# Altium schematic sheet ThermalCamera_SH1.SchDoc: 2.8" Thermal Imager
size 647 x 419 mm; Author: Steve Hageman; DrawnBy: Steve Hageman; DocumentNumber: 2019-02-21; Revision: B1; SheetNumber: 1; SheetTotal: 1; PageSetup: Record=PageOptions¦CenterHorizontal=True¦CenterVertical=True¦PrintScale=1.00¦XCorrection=1.00¦YCorrection=1.00¦PrintKind=0¦BorderSize=5000000¦LeftOffset=0¦BottomOffset=0¦Orientation=2¦PaperLength=1000¦PaperWidth=1000¦Scale=100¦PaperSource=15¦PrintQuality=600¦MediaType=1¦DitherType=10¦PaperKind=Letter¦PrintScaleMode=1
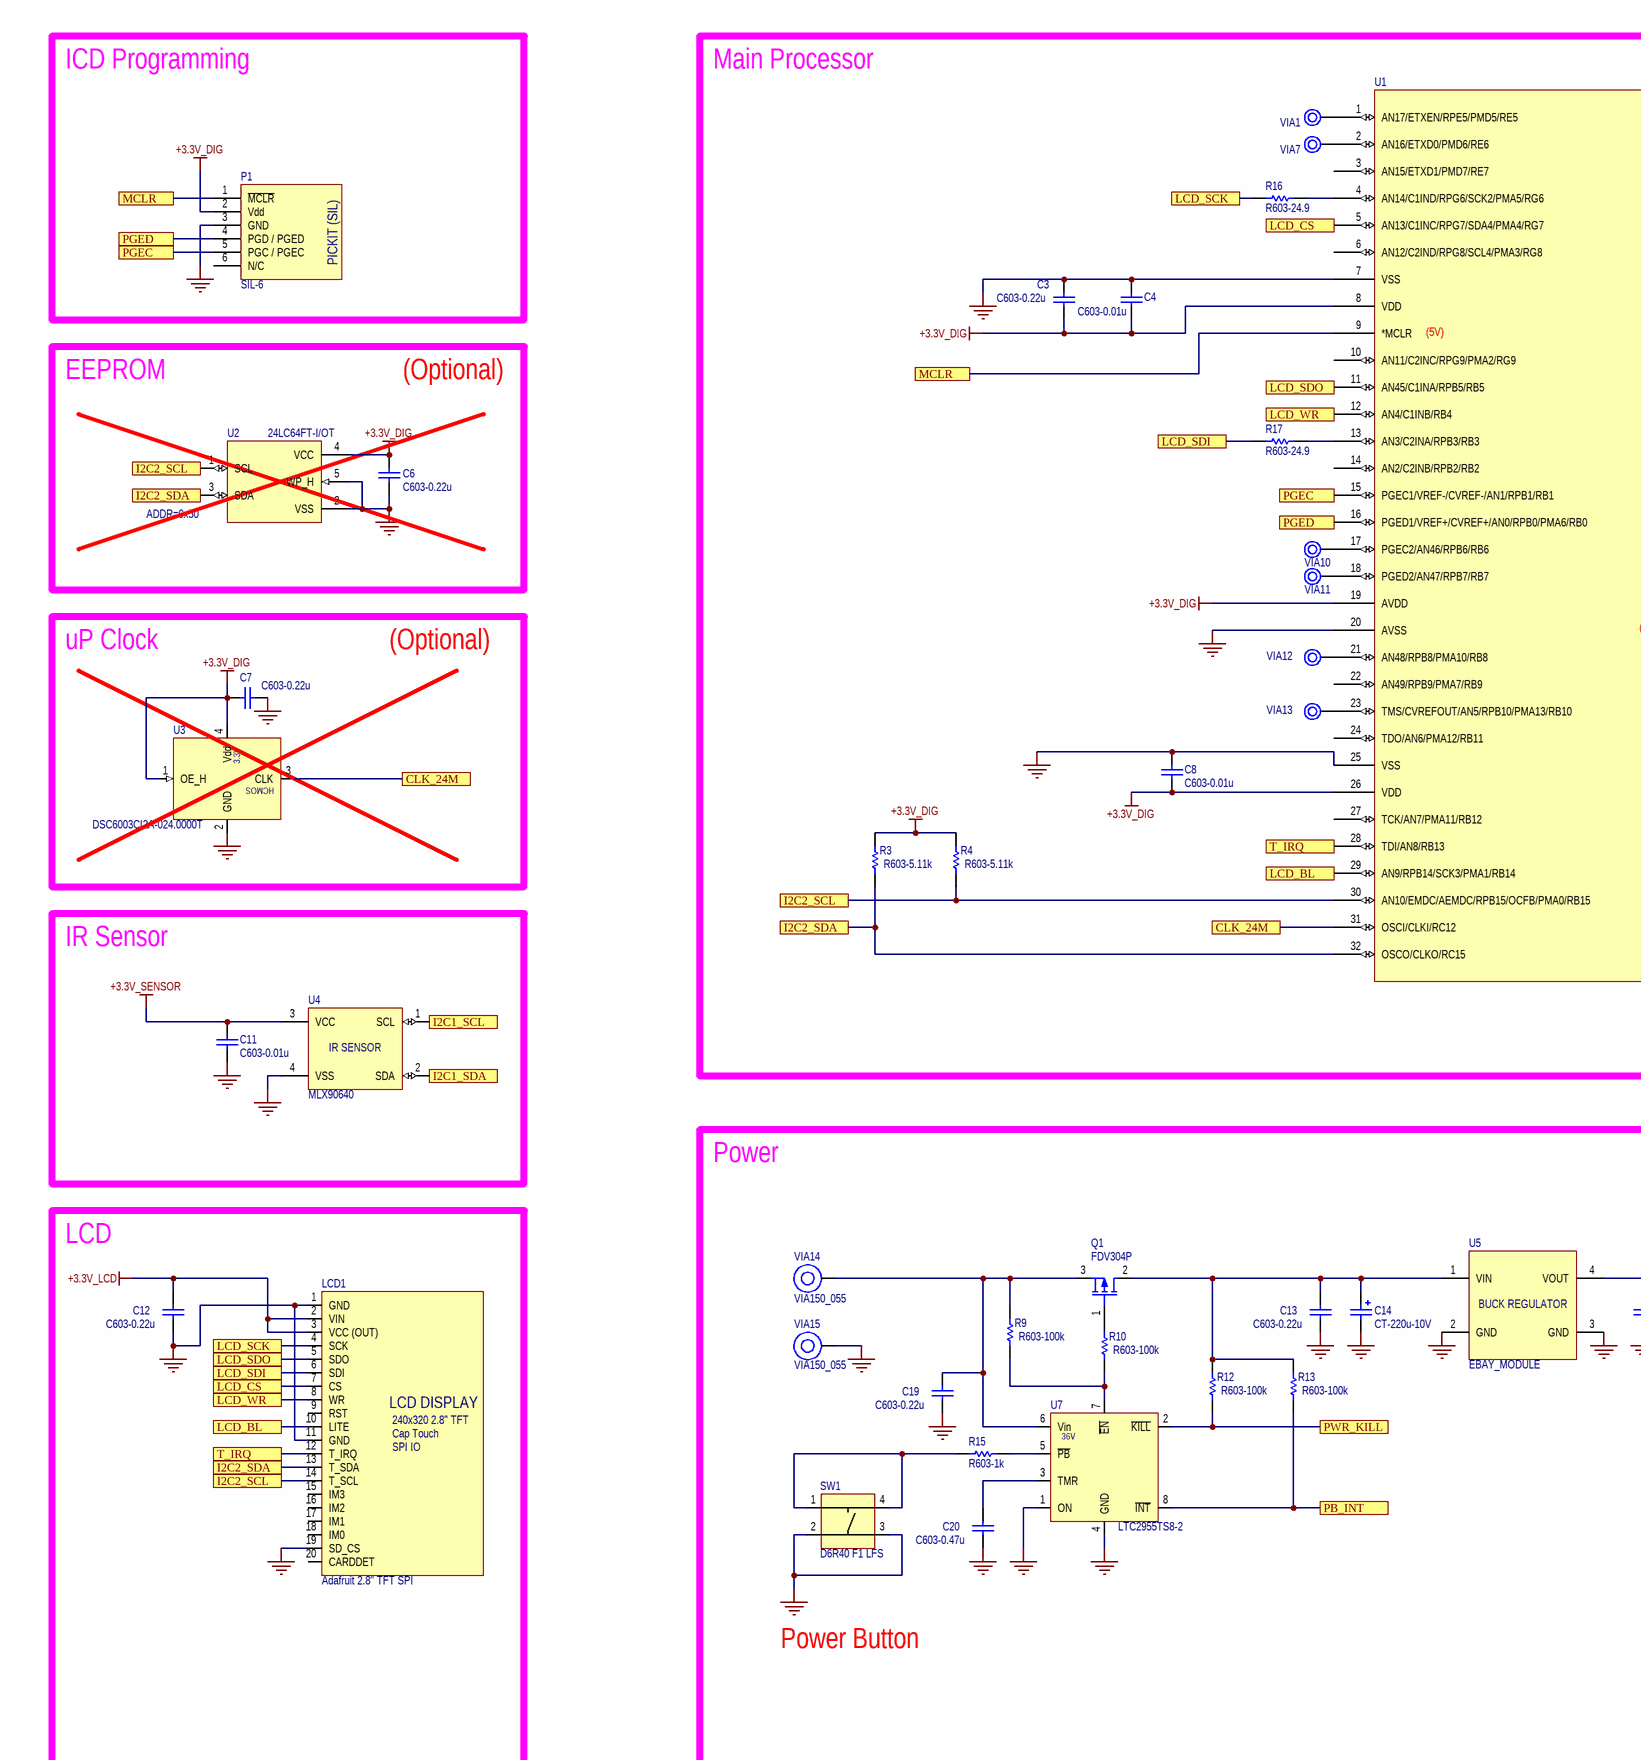
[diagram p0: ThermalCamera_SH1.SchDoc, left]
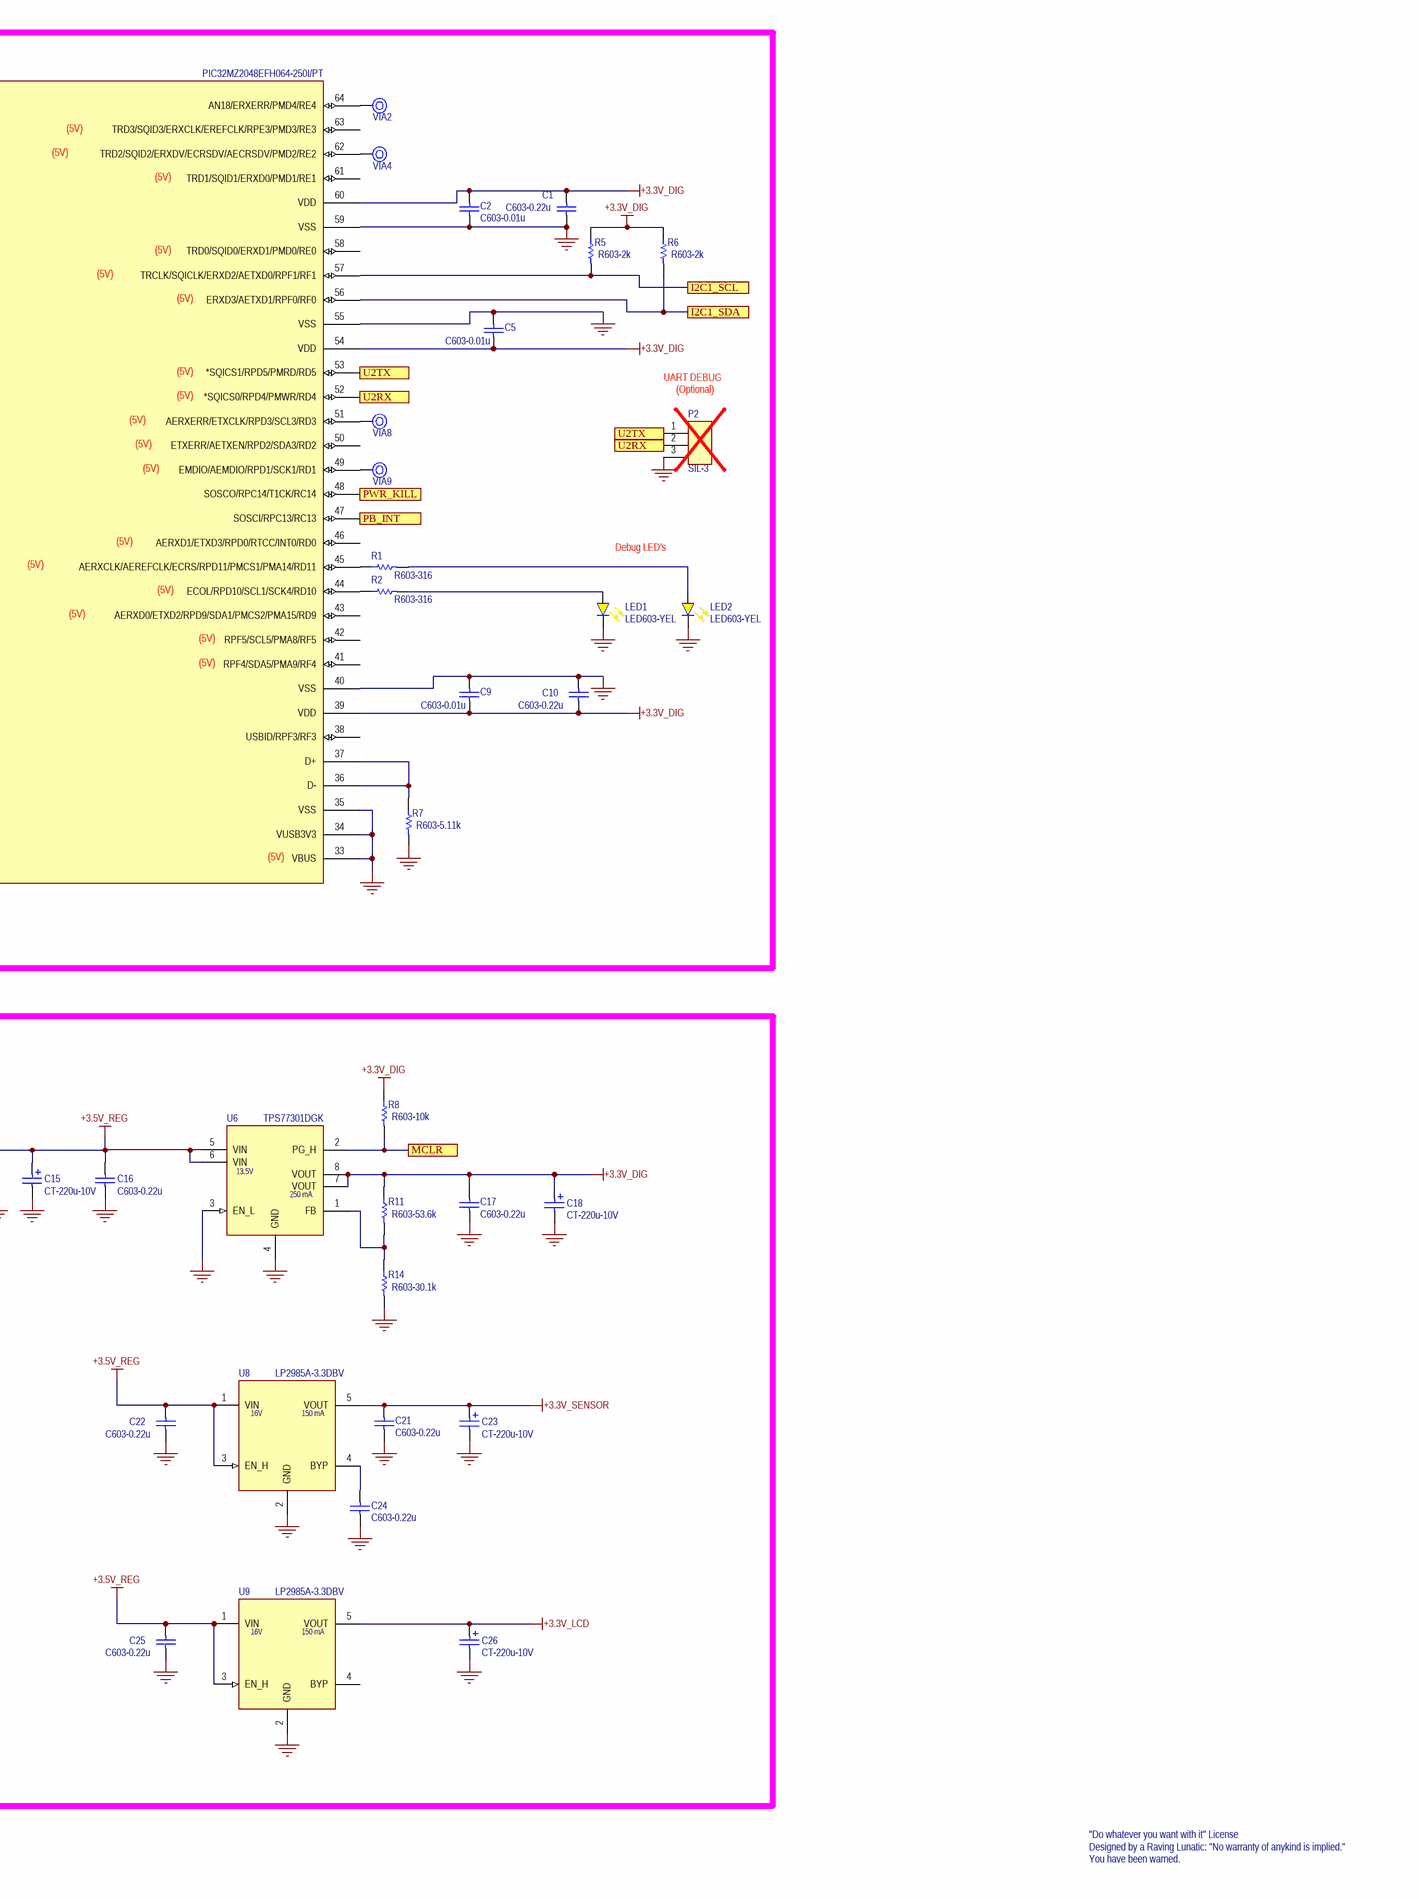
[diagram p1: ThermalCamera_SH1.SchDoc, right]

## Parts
?  (no value)  (graphical)
C1  C603-0.22u  [0603]
C2  C603-0.01u  [0603]
C3  C603-0.22u  [0603]
C4  C603-0.01u  [0603]
C5  C603-0.01u  [0603]
C6  C603-0.22u  [0603]
C7  C603-0.22u  [0603]
C8  C603-0.01u  [0603]
C9  C603-0.01u  [0603]
C10  C603-0.22u  [0603]
C11  C603-0.01u  [0603]
C12  C603-0.22u  [0603]
C13  C603-0.22u  [0603]
C14  CT-220u-10V  [6032-28]
C15  CT-220u-10V  [6032-28]
C16  C603-0.22u  [0603]
C17  C603-0.22u  [0603]
C18  CT-220u-10V  [6032-28]
C19  C603-0.22u  [0603]
C20  C603-0.47u  [0603]
C21  C603-0.22u  [0603]
C22  C603-0.22u  [0603]
C23  CT-220u-10V  [6032-28]
C24  C603-0.22u  [0603]
C25  C603-0.22u  [0603]
C26  CT-220u-10V  [6032-28]
LCD1  Adafruit 2.8" TFT SPI  [Header_SIL_20]
LED1  LED603-YEL  [0603LED-YEL]
LED2  LED603-YEL  [0603LED-YEL]
P1  SIL-6  [ProgHeader_SIL]
P2  SIL-3  [Header_SIL_3]
Q1  FDV304P  [SOT23]
R1  R603-316  [0603]
R2  R603-316  [0603]
R3  R603-5.11k  [0603]
R4  R603-5.11k  [0603]
R5  R603-2k  [0603]
R6  R603-2k  [0603]
R7  R603-5.11k  [0603]
R8  R603-10k  [0603]
R9  R603-100k  [0603]
R10  R603-100k  [0603]
R11  R603-53.6k  [0603]
R12  R603-100k  [0603]
R13  R603-100k  [0603]
R14  R603-30.1k  [0603]
R15  R603-1k  [0603]
R16  R603-24.9  [0603]
R17  R603-24.9  [0603]
SW1  D6R40 F1 LFS  [D6R40_F1_LFS]
U1  PIC32MZ2048EFH064-250I/PT  [TQFP64_10x10MC]
U2  24LC64FT-I/OT  [SOT23_5]
U3  DSC6003CI2A-024.0000T  [MICREL-3.2x2.5MM-OSC]
U4  MLX90640  [MLX90640]
U5  EBAY_MODULE  [BUCK_MODULE]
U6  TPS77301DGK  [DGK8]
U7  LTC2955TS8-2  [SOT23_8]
U8  LP2985A-3.3DBV  [DBV]
U9  LP2985A-3.3DBV  [DBV]
VIA1  VIA038_025  [VIA038_25]  (value not drawn)  (no BOM)
VIA2  VIA038_025  [VIA038_25]  (value not drawn)  (no BOM)
VIA4  VIA038_025  [VIA038_25]  (value not drawn)  (no BOM)
VIA7  VIA038_025  [VIA038_25]  (value not drawn)  (no BOM)
VIA8  VIA038_025  [VIA038_25]  (value not drawn)  (no BOM)
VIA9  VIA038_025  [VIA038_25]  (value not drawn)  (no BOM)
VIA10  VIA038_025  [VIA038_25]  (value not drawn)  (no BOM)
VIA11  VIA038_025  [VIA038_25]  (value not drawn)  (no BOM)
VIA12  VIA038_025  [VIA038_25]  (value not drawn)  (no BOM)
VIA13  VIA038_025  [VIA038_25]  (value not drawn)  (no BOM)
VIA14  VIA150_055  [VIA150_055]  (no BOM)
VIA15  VIA150_055  [VIA150_055]  (no BOM)

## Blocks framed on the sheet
ICD Programming: P1
Main Processor: C1-C5 C8-C10 LED1 LED2 P2 R1-R7 R16 R17 U1 VIA1 VIA2 VIA4 VIA7-VIA13
IR Sensor: C11 U4
LCD: C12 LCD1

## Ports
CLK_24M, I2C1_SCL, I2C1_SDA, I2C2_SCL, I2C2_SDA, LCD_BL, LCD_CS, LCD_SCK, LCD_SDI, LCD_SDO, LCD_WR, MCLR, PB_INT, PGEC, PGED, PWR_KILL, T_IRQ, U2RX, U2TX

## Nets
+3.3V_DIG: C1.1 C2.1 C3.2 C4.2 C5.2 C6.2 C7.2 C8.2 C9.2 C10.2 C17.1 C18.1 P1.2(Vdd) R3.1 R4.1 R5.1 R6.1 R8.1 R11.1 U1.8(VDD) U1.19(AVDD) U1.26(VDD) U1.39(VDD) U1.54(VDD) U1.60(VDD) U2.4(VCC) U3.1(OE_H) U3.4(Vdd) U6.7(VOUT) U6.8(VOUT)
+3.3V_LCD: C12.2 C26.1 LCD1.2(VIN) LCD1.3(VCC_(OUT)) U9.5(VOUT)
+3.3V_SENSOR: C11.1 C21.1 C23.1 U4.3(VCC) U8.5(VOUT)
+3.5V_REG: C15.1 C16.1 C22.1 C25.1 U5.4(VOUT) U6.5(VIN) U6.6(VIN) U8.1(VIN) U8.3(EN_H) U9.1(VIN) U9.3(EN_H)
GND: C1.2 C2.2 C3.1 C4.1 C5.1 C6.1 C7.1 C8.1 C9.1 C10.1 C11.2 C12.1 C13.2 C14.2 C15.2 C16.2 C17.2 C18.2 C19.2 C20.2 C21.2 C22.2 C23.2 C24.2 C25.2 C26.2 LCD1.1(GND) LCD1.11(GND) LCD1.19(SD_CS) LED1.1(K) LED2.1(K) P1.3(GND) P2.3 R7.2 R14.2 SW1.2 SW1.3 U1.7(VSS) U1.20(AVSS) U1.25(VSS) U1.33(VBUS) U1.34(VUSB3V3) U1.35(VSS) U1.40(VSS) U1.55(VSS) U1.59(VSS) U2.2(VSS) U2.5(WP_H) U3.2(GND) U4.4(VSS) U5.2(GND) U5.3(GND) U6.3(EN_L) U6.4(GND) U7.1(ON) U7.4(GND) U8.2(GND) U9.2(GND) VIA15.1
CLK_24M: U1.31(OSCI/CLKI/RC12) U3.3(CLK) ; port CLK_24M
I2C1_SCL: R5.2 U1.57(TRCLK/SQICLK/ERXD2/AETXD0/RPF1/RF1) U4.1(SCL) ; port I2C1_SCL
I2C1_SDA: R6.2 U1.56(ERXD3/AETXD1/RPF0/RF0) U4.2(SDA) ; port I2C1_SDA
I2C2_SCL: LCD1.14(T_SCL) R4.2 U1.30(AN10/EMDC/AEMDC/RPB15/OCFB/PMA0/RB15) U2.1(SCL) ; port I2C2_SCL
I2C2_SDA: LCD1.13(T_SDA) R3.2 U1.32(OSCO/CLKO/RC15) U2.3(SDA) ; port I2C2_SDA
LCD_BL: LCD1.10(LITE) U1.29(AN9/RPB14/SCK3/PMA1/RB14) ; port LCD_BL
LCD_CS: LCD1.7(CS) U1.5(AN13/C1INC/RPG7/SDA4/PMA4/RG7) ; port LCD_CS
LCD_SCK: LCD1.4(SCK) R16.1 ; port LCD_SCK
LCD_SDI: LCD1.6(SDI) R17.1 ; port LCD_SDI
LCD_SDO: LCD1.5(SDO) U1.11(AN45/C1INA/RPB5/RB5) ; port LCD_SDO
LCD_WR: LCD1.8(WR) U1.12(AN4/C1INB/RB4) ; port LCD_WR
MCLR: P1.1(~{MCLR}) R8.2 U1.9(*MCLR) U6.2(PG_H) ; port MCLR
PB_INT: R13.2 U1.47(SOSCI/RPC13/RC13) U7.8(~{INT}) ; port PB_INT
PGEC: P1.5(PGC_/_PGEC) U1.15(PGEC1/VREF-/CVREF-/AN1/RPB1/RB1) ; port PGEC
PGED: P1.4(PGD_/_PGED) U1.16(PGED1/VREF+/CVREF+/AN0/RPB0/PMA6/RB0) ; port PGED
PWR_KILL: R12.2 U1.48(SOSCO/RPC14/T1CK/RC14) U7.2(~{KILL}) ; port PWR_KILL
T_IRQ: LCD1.12(T_IRQ) U1.28(TDI/AN8/RB13) ; port T_IRQ
U2RX: P2.2 U1.52(*SQICS0/RPD4/PMWR/RD4) ; port U2RX
U2TX: P2.1 U1.53(*SQICS1/RPD5/PMRD/RD5) ; port U2TX
NetC13_1: C13.1 C14.1 Q1.2(D) R12.1 R13.1 U5.1(VIN)
NetC19_1: C19.1 Q1.3(S) R9.1 U7.6(Vin) VIA14.1
NetC20_1: C20.1 U7.3(TMR)
NetC24_1: C24.1 U8.4(BYP)
NetLED1_2: LED1.2(A) R2.2
NetLED2_2: LED2.2(A) R1.2
NetQ1_1: Q1.1(G) R10.1
NetR1_1: R1.1 U1.45(AERXCLK/AEREFCLK/ECRS/RPD11/PMCS1/PMA14/RD11)
NetR2_1: R2.1 U1.44(ECOL/RPD10/SCL1/SCK4/RD10)
NetR7_1: R7.1 U1.36(D-) U1.37(D+)
NetR9_2: R9.2 R10.2 U7.7(~{EN})
NetR11_2: R11.2 R14.1 U6.1(FB)
NetR15_1: R15.1 SW1.1 SW1.4
NetR15_2: R15.2 U7.5(~{PB})
NetR16_2: R16.2 U1.4(AN14/C1IND/RPG6/SCK2/PMA5/RG6)
NetR17_2: R17.2 U1.13(AN3/C2INA/RPB3/RB3)
NetU1_1: U1.1(AN17/ETXEN/RPE5/PMD5/RE5) VIA1.1
NetU1_2: U1.2(AN16/ETXD0/PMD6/RE6) VIA7.1
NetU1_17: U1.17(PGEC2/AN46/RPB6/RB6) VIA10.1
NetU1_18: U1.18(PGED2/AN47/RPB7/RB7) VIA11.1
NetU1_21: U1.21(AN48/RPB8/PMA10/RB8) VIA12.1
NetU1_23: U1.23(TMS/CVREFOUT/AN5/RPB10/PMA13/RB10) VIA13.1
NetU1_49: U1.49(EMDIO/AEMDIO/RPD1/SCK1/RD1) VIA9.1
NetU1_51: U1.51(AERXERR/ETXCLK/RPD3/SCL3/RD3) VIA8.1
NetU1_62: U1.62(TRD2/SQID2/ERXDV/ECRSDV/AECRSDV/PMD2/RE2) VIA4.1
NetU1_64: U1.64(AN18/ERXERR/PMD4/RE4) VIA2.1

Not connected (* = marked no-connect by the designer): LCD1 9(RST) 15(IM3) 16(IM2) 17(IM1) 18(IM0) 20(CARDDET); P1 6(N/C); U1 3(AN15/ETXD1/PMD7/RE7) 6(AN12/C2IND/RPG8/SCL4/PMA3/RG8) 10(AN11/C2INC/RPG9/PMA2/RG9) 14(AN2/C2INB/RPB2/RB2) 22(AN49/RPB9/PMA7/RB9) 24(TDO/AN6/PMA12/RB11) 27(TCK/AN7/PMA11/RB12) 38(USBID/RPF3/RF3) 41(RPF4/SDA5/PMA9/RF4) 42(RPF5/SCL5/PMA8/RF5) 43(AERXD0/ETXD2/RPD9/SDA1/PMCS2/PMA15/RD9) 46(AERXD1/ETXD3/RPD0/RTCC/INT0/RD0) 50(ETXERR/AETXEN/RPD2/SDA3/RD2) 58(TRD0/SQID0/ERXD1/PMD0/RE0) 61(TRD1/SQID1/ERXD0/PMD1/RE1) 63(TRD3/SQID3/ERXCLK/EREFCLK/RPE3/PMD3/RE3); U9 4(BYP)

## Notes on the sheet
- EEPROM
- (Optional)
- UART DEBUG
- (near P2) (Optional)
- (near U2) ADDR=0x50
- uP Clock
- Debug LED's
- Power
- Power Button
- "Do whatever you want with it" License
- Designed by a Raving Lunatic: "No warranty of anykind is implied."
- You have been warned.

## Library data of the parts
? = Title Block AnalogHome
C1-C13 C16 C17 C19-C22 C24 C25 = C0603-0.22u: 0.22uF 50V X7R 603 Capacitor
C14 C15 C18 C23 C26 = CT-220u-10V: 220uF/10V Tant
LCD1 = Adafruit 2.8" TFT SPI: 240x320 TFT LCD
LED1 LED2 = LED603-YEL: Yellow LED
P1 = Prog PICKIT Header (SIL): PICKIT Programming Header (SIL)
P2 = Header_SIL_3: Header SIL 3 Pin
Q1 = FDV304P: PMOS 25V, 1.1 Ohm, 460mA
R1-R17 = R0603: 0603 Resistor
SW1 = PB-PANEL_1: PB TACTILE THROUGH HOLE
U1 = PIC32MZ2048EFH064-250I/PT: PIC32MZ 250 MHz TQFP
U2 = 24LC64FT-I/OT: 64K I2C EEPROM
U3 = MEMS 24MHz: 24MHz CLOCK 1.8-3.3V Low Power
U4 = MLX90640: IR SENSOR 55 DEGREE
U5 = EBAY_BUCK_MODULE: EBAY BUCK MODULE
U6 = TPS77301DGK: 250mA LDO W/Reset Output
U7 = LTC2955TS8-2: PushButton Controller
U8 U9 = LP2985A: 150mA LDO W/ENABLE
VIA1 VIA2 VIA4 VIA7-VIA13 = VIA038_025: 38/25 Via Only
VIA14 VIA15 = VIA150_055: 150 / 55 Via Only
